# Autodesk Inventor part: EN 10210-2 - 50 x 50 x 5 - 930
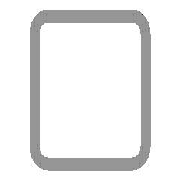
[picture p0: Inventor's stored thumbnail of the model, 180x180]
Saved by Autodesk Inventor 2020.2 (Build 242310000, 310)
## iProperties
_CCFamilyMember: 16
_CCFamilyDisplayName: DIN EN 10210-2 (USAS B17.1 quadratisch) - Rohrleitung — In Klammern angegebene Größen wurden aufgehoben
_FrameMemberDoc: Frame Member File
_Version: 15.0.0
_GetPNFromCC: 1
Created: 2019-01
Part Number: EN 10210-2 - 50 x 50 x 5 - 930
Material: Stahl, weich
Description: Rohrleitung
Document SubType Name: Modeling
Standard: DIN
Designer: lutzd
Standard Revision: 2006-07
Standards Organization: DIN
Language: de-DE
Size Designation: 50 x 50 x 5
Categories: <MemberInstance><Categories><Category DisplayName="Profile" InternalName="089c4875-fa83-4c05-b084-43b9cc11f5ed" Mnemonic="GRDR"><CategoryParameter DisplayName="
Stock Number: 50 x 50 x 5
Mass: 6374.61 g
Surface Area: 3165.88 cm^2
Volume: 812.053 cm^3
Density: 7.85 g/cm^3
Appearance: Semi-Polished(8)
G_L: 930,000 mm
G_W: 50,000 mm
G_H: 50,000 mm
DocNumber: ADSK-014270
Folder: .
Dimensions: 50x50x930 mm
Mass: 6,375 kg
+FB0BDD17-589C-49BF-A2E6-6372D0C1EE81+SCHNITTDETAIL1: Schnittwinkel 90,00 grd
+81EB50DB-66BF-4D54-B0E0-371CDA8D4FED+SCHNITTDETAIL2: Schnittwinkel 90,00 grd
VLT_Material: Stahl, weich
IsCustomPart: 1
Title: Profil-Bauteil
Author: lutzd
Revision Number: -
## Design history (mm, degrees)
node "Startebene"
node "Endebene"
sketch "Skizze"
  geometry: L1 (-25, -17.5)-(-25, 17.5); L2 (-17.5, 25)-(17.5, 25); L3 (25, 17.5)-(25, -17.5); L4 (17.5, -25)-(-17.5, -25); L5 (-15, 20)-(15, 20); L6 (20, 15)-(20, -15); L7 (15, -20)-(-15, -20); L8 (-20, -15)-(-20, 15); L9 (0, 37.175)-(0, -37.175) reference; L10 (-37.175, 0)-(37.175, 0) reference; A1 r 7.5 centre (-17.5, -17.5) between (-25, -17.5) and (-17.5, -25); A2 r 7.5 centre (-17.5, 17.5) between (-17.5, 25) and (-25, 17.5); A3 r 7.5 centre (17.5, 17.5) between (25, 17.5) and (17.5, 25); A4 r 7.5 centre (17.5, -17.5) between (17.5, -25) and (25, -17.5); A5 r 5 centre (-15, -15) between (-20, -15) and (-15, -20); A6 r 5 centre (-15, 15) between (-15, 20) and (-20, 15); A7 r 5 centre (15, 15) between (20, 15) and (15, 20); A8 r 5 centre (15, -15) between (15, -20) and (20, -15)
  constraints: 16 end point, 16 point on circle, 16 tangent, 8 centre point, 6 equal radius, 4 parallel, 2 perpendicular, 2 other
  dimensions: "d7" = 7.5 radius of A1 (= G_IR); "d10" = 50 distance between parallel lines of L2 L4 (= G_H); "d11" = 50 distance between parallel lines of L1 L3 (= G_W); "d12" = 5 distance between parallel lines of L3 L6 (= G_T); "d15" = 25 distance between parallel lines of L2 L10 (= 0.5 x d10); "d16" = 25 distance between parallel lines of L9 L3 (= 0.5 x d11); "d19" = 5 radius of A5 (= G_T); "d20" = 5 distance between parallel lines of L4 L7 (= G_T)
extrude "Körper" new body sketch "Skizze" stored distance "d3" = 930 (= G_L); taper "d4" = 0 deg
node "Driven Length"
  sketch "Sketch3"
    geometry: L1 (0, 0)-(10, 0) reference
    constraints: 2 end point, 1 horizontal
  workplane "Work Plane3"
  sketch "Sketch4"
    geometry: L1 (-2, 50)-(12, 50) reference; L2 (-2, 980)-(12, 980) reference
    dimensions: "d18" = 930 distance between parallel lines of L1 L2 (derived)
workplane "Arbeitsebene4"
feature "Trennen1"
workplane "Arbeitsebene5"
feature "Trennen2"
body "Solid1"
other parameters: "G_W" = 50 [user parameter; used in 1 equation term], "G_H" = 50 [user parameter; used in 1 equation term], "G_T" = 5 [user parameter; used in 3 equation terms], "G_IR" = 7.5 [user parameter; used in 1 equation term], "G_L" = 930 (= d18) [user parameter; used in 1 equation term], "d17" = 90 deg
